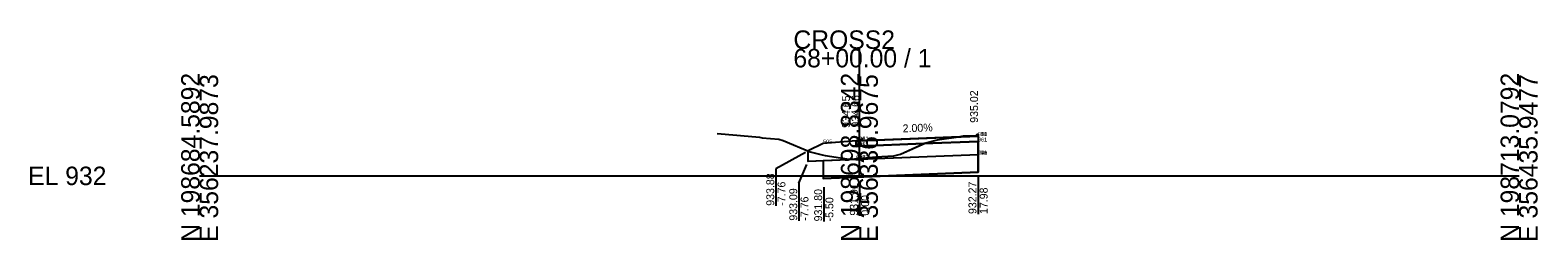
# Model space of a CAD drawing. Extents: x -26 to 203, y -10 to 14021.
# Drawn here: x -25.7 to 202.8, y 8990.3 to 9022.1 of the extents above; entities that cross this region are included whole.
import ezdxf

# ---------------------------------------------------------------- set-up
doc = ezdxf.new("R2010")
doc.units = 0
for name, color, linetype in [('Default', 7, 'Continuous'), ('P_E_XS_Ground', 7, 'Continuous'), ('P_XS', 7, 'Continuous'), ('P_XS_Bold', 7, 'Continuous'), ('P_XS_EAR_CommonGrnd', 7, 'Continuous'), ('P_XS_Lane', 7, 'Continuous'), ('P_XS_Rock', 7, 'Continuous')]:
    doc.layers.add(name, color=color, linetype=linetype)

msp = doc.modelspace()

# ---------------------------------------------------------------- linework, layer by layer
at = {"layer": 'Default'}
for p, q in [((100, 9000), (100, 9019.24)), ((0, 9000), (100, 9000)), ((100, 9000), (200, 9000))]:
    msp.add_line(p, q, dxfattribs=at)
at = {"layer": 'P_E_XS_Ground'}
for p, q in [((78.43, 9006.41), (81.43, 9006.17)), ((81.43, 9006.17), (81.97, 9006.1)), ((81.97, 9006.1), (84.84, 9005.85)), ((84.84, 9005.85), (85.26, 9005.77)), ((85.26, 9005.77), (87.81, 9005.56)), ((87.81, 9005.56), (88.44, 9005.34)), ((88.44, 9005.34), (92.54, 9003.65)), ((106.22, 9003.29), (110.05, 9005)), ((110.05, 9005), (111.85, 9005.47)), ((111.85, 9005.47), (112.16, 9005.51)), ((112.16, 9005.51), (115.01, 9005.89)), ((115.01, 9005.89), (115.73, 9006.03)), ((115.73, 9006.03), (117.69, 9006.02)), ((117.69, 9006.02), (117.85, 9006.29)), ((117.85, 9006.29), (118.06, 9006.29)), ((92.54, 9003.65), (94.36, 9003.2)), ((94.36, 9003.2), (94.81, 9003.08)), ((94.81, 9003.08), (98.43, 9002.55)), ((98.43, 9002.55), (100, 9002.64)), ((100, 9002.64), (100.47, 9002.66)), ((100.47, 9002.66), (102.48, 9002.89)), ((102.48, 9002.89), (105.24, 9003.05)), ((105.24, 9003.05), (106.22, 9003.29))]:
    msp.add_line(p, q, dxfattribs=at)
at = {"layer": 'P_XS'}
for p, q in [((99.5, 9005.3), (99.5, 9004.47)), ((99.5, 9004.47), (100, 9004.49)), ((117.98, 9005.2), (99.97, 9004.49)), ((117.98, 9006.04), (117.98, 9005.2)), ((117.98, 9003.2), (117.98, 9005.2)), ((92.24, 9002.17), (92.24, 9003.77)), ((99.5, 9002.47), (92.24, 9002.17)), ((94.5, 9002.27), (94.5, 8999.6)), ((99.5, 9002.47), (100, 9002.49)), ((117.98, 9003.2), (99.97, 9002.49)), ((117.98, 9003.2), (117.98, 9000.54)), ((117.98, 9000.54), (94.5, 8999.6))]:
    msp.add_line(p, q, dxfattribs=at)
at = {"layer": 'P_XS_EAR_CommonGrnd'}
for points in [[(105.24, 9003.05), (106.22, 9003.29), (109.78, 9004.88), (100, 9004.49), (99.97, 9004.49), (99.5, 9004.47), (99.5, 9005.3), (94.5, 9004.9), (92.24, 9003.77), (92.54, 9003.65), (94.36, 9003.2), (94.81, 9003.08), (98.43, 9002.55), (100, 9002.64), (100.47, 9002.66), (102.48, 9002.89)], [(105.24, 9003.05), (106.22, 9003.29), (109.78, 9004.88), (117.98, 9005.2), (117.98, 9003.2), (100, 9002.49), (99.97, 9002.49), (99.5, 9002.47), (94.5, 9002.27), (92.24, 9002.17), (92.24, 9003.77), (92.54, 9003.65), (94.36, 9003.2), (94.81, 9003.08), (98.43, 9002.55), (100, 9002.64), (100.47, 9002.66), (102.48, 9002.89)], [(99.5, 9004.47), (99.97, 9004.49), (100, 9004.49), (109.78, 9004.88), (110.05, 9005), (111.85, 9005.47), (112.16, 9005.51), (115.01, 9005.89), (115.23, 9005.93), (100, 9005.32), (99.5, 9005.3)], [(115.23, 9005.93), (117.45, 9006.02), (117.69, 9006.02), (117.7, 9006.03), (117.98, 9006.04), (117.98, 9005.2), (109.78, 9004.88), (110.05, 9005), (111.85, 9005.47), (112.16, 9005.51), (115.01, 9005.89)], [(115.23, 9005.93), (117.45, 9006.02), (115.73, 9006.03)], [(117.45, 9006.02), (117.69, 9006.02), (117.7, 9006.03)], [(117.98, 9006.04), (117.98, 9006.29), (117.85, 9006.29), (117.7, 9006.03)], [(94.5, 9002.27), (94.5, 8999.6), (117.98, 9000.54), (117.98, 9003.2), (100, 9002.49), (99.97, 9002.49), (99.5, 9002.47)]]:
    msp.add_lwpolyline(points, close=True, dxfattribs=at)
at = {"layer": 'P_XS_Lane'}
for p, q in [((94.5, 9004.9), (92.24, 9003.77)), ((99.5, 9005.3), (94.5, 9004.9)), ((99.5, 9005.3), (100, 9005.32)), ((100, 9005.32), (117.98, 9006.04)), ((117.98, 9006.04), (117.98, 9006.29))]:
    msp.add_line(p, q, dxfattribs=at)
at = {"layer": 'P_XS_Rock'}
for p, q in [((91.85, 9003.55), (87.34, 9001.06)), ((87.34, 9001.06), (87.34, 8995.47)), ((90.83, 8998.89), (92.05, 9001.73)), ((117.99, 8999.82), (117.99, 8994.22)), ((90.83, 8998.89), (90.83, 8993.2)), ((94.6, 8998.31), (94.6, 8993.1)), ((100.01, 8998.78), (100.01, 8993.96))]:
    msp.add_line(p, q, dxfattribs=at)

# ---------------------------------------------------------------- texts
at = {"layer": 'Default'}
for s, p in [('CROSS2', (90, 9019.24)), ('68+00.00 / 1', (90, 9016.44)), ('EL 932', (-26, 8998.6))]:
    msp.add_text(s, height=2.8, dxfattribs=at).set_placement(p)
for s, p in [('N 198684.5892', (0, 8990)), ('E 356237.9873', (2.8, 8990)), ('N 198698.8342', (100, 8990)), ('E 356336.9675', (102.8, 8990)), ('N 198713.0792', (200, 8990)), ('E 356435.9477', (202.8, 8990))]:
    msp.add_text(s, height=2.8, rotation=90, dxfattribs=at).set_placement(p)
at = {"layer": 'P_XS_Bold'}
for s, p in [('951', (117.98, 9006.04)), ('9', (117.98, 9006.04)), ('900', (117.98, 9006.04)), ('910', (117.98, 9006.04)), ('505', (94.5, 9004.9)), ('951', (99.5, 9005.3)), ('9', (99.5, 9005.3)), ('900', (99.5, 9005.3)), ('961', (99.5, 9004.47)), ('962', (99.97, 9004.49)), ('952', (100, 9005.32)), ('952', (100, 9005.32)), ('962', (100, 9004.49)), ('961', (117.98, 9005.2)), ('971', (99.5, 9002.47)), ('998', (99.5, 9002.47)), ('972', (99.97, 9002.49)), ('972', (100, 9002.49)), ('540', (117.98, 9003.2)), ('971', (117.98, 9003.2)), ('998', (117.98, 9003.2))]:
    msp.add_text(s, height=0.6, dxfattribs=at).set_placement(p)
at = {"layer": 'P_XS_Rock'}
for s, rotation, p in [('934.65', 90, (98.56, 9007.27)), ('934.66', 90, (100, 9007.32)), ('934.66', 90, (100, 9007.32)), ('934.66', 90, (100, 9007.32)), ('934.66', 90, (100, 9007.32)), ('935.02', 90, (117.98, 9008.04)), ('2.00%', 2.2906, (106.58, 9006.58)), ('933.88', 90, (87.09, 8995.47)), ('-7.76', 90, (88.79, 8995.47)), ('933.09', 90, (90.58, 8993.21)), ('931.80', 90, (94.35, 8993.1)), ('931.91', 90, (99.76, 8993.97)), ('932.27', 90, (117.74, 8994.22)), ('17.98', 90, (119.44, 8994.22)), ('-7.76', 90, (92.28, 8993.21)), ('-5.50', 90, (96.05, 8993.1)), ('0.00', 90, (101.46, 8993.97))]:
    msp.add_text(s, height=1.2, rotation=rotation, dxfattribs=at).set_placement(p)

doc.saveas('drawing.dxf')
